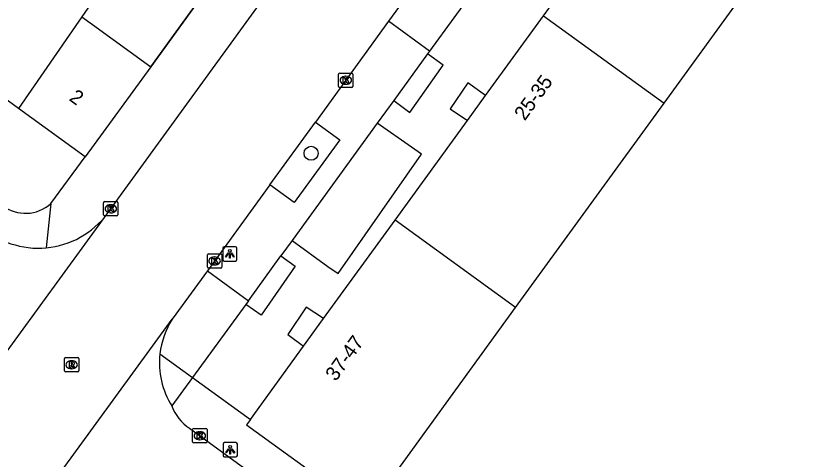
# Model space of a CAD drawing. Extents: x 159675 to 160530, y 382179 to 382901.
# Drawn here: x 160284.3 to 160339.1, y 382588.5 to 382619.4 of the extents above; entities that cross this region are included whole.
import ezdxf

# ---------------------------------------------------------------- set-up
doc = ezdxf.new("R2010")
doc.units = 0
for name, color, linetype in [('IMGEO_Boom', 7, 'Continuous'), ('IMGEO_Kolk', 7, 'Continuous'), ('IMGEO_Lichtpunt', 7, 'Continuous'), ('IMGEO_Muur', 7, 'Continuous'), ('IMGEO_Pand', 7, 'Continuous'), ('IMGEO_Pand_nummerreeks', 7, 'Continuous'), ('IMGEO_Rijbaan_lokaal_gesloten', 7, 'Continuous'), ('IMGEO_Rijbaan_lokaal_open', 7, 'Continuous'), ('IMGEO_Rioolput', 7, 'Continuous'), ('IMGEO_Voetpad_open', 7, 'Continuous')]:
    doc.layers.add(name, color=color, linetype=linetype)

msp = doc.modelspace()

# ---------------------------------------------------------------- linework, layer by layer
at = {"layer": 'IMGEO_Boom'}
msp.add_circle((160304.817, 382609.777), 0.489, dxfattribs=at)
at = {"layer": 'IMGEO_Kolk'}
for p, q in [((160306.806, 382615.366), (160307.658, 382615.366)), ((160306.731, 382614.44), (160306.731, 382615.292)), ((160307.219, 382615.146), (160307.244, 382615.146)), ((160307.732, 382615.292), (160307.732, 382614.44)), ((160307.658, 382614.366), (160306.806, 382614.366)), ((160307.242, 382614.586), (160307.217, 382614.586)), ((160290.37, 382605.485), (160290.37, 382606.337)), ((160290.445, 382606.411), (160291.297, 382606.411)), ((160290.858, 382606.191), (160290.883, 382606.191)), ((160291.371, 382606.337), (160291.371, 382605.485)), ((160290.881, 382605.631), (160290.856, 382605.631)), ((160291.297, 382605.411), (160290.445, 382605.411)), ((160297.671, 382602.781), (160298.523, 382602.781)), ((160297.596, 382601.855), (160297.596, 382602.707)), ((160298.084, 382602.561), (160298.109, 382602.561)), ((160298.597, 382602.707), (160298.597, 382601.855)), ((160298.523, 382601.781), (160297.671, 382601.781)), ((160298.107, 382602.001), (160298.082, 382602.001)), ((160296.569, 382589.673), (160296.569, 382590.525)), ((160296.644, 382590.599), (160297.496, 382590.599)), ((160297.057, 382590.379), (160297.082, 382590.379)), ((160297.57, 382590.525), (160297.57, 382589.673)), ((160297.496, 382589.599), (160296.644, 382589.599)), ((160297.08, 382589.819), (160297.055, 382589.819))]:
    msp.add_line(p, q, dxfattribs=at)
for points in [[(160306.806, 382615.366), (160307.658, 382615.366)], [(160306.731, 382614.44), (160306.731, 382615.292)], [(160307.052, 382615.066), (160307.175, 382615.066), (160307.175, 382614.915), (160307.305, 382615.066), (160307.469, 382615.066), (160307.323, 382614.915), (160307.476, 382614.666), (160307.324, 382614.666), (160307.239, 382614.83), (160307.175, 382614.763), (160307.175, 382614.666), (160307.052, 382614.666), (160307.052, 382615.066)], [(160307.732, 382615.292), (160307.732, 382614.44)], [(160307.658, 382614.366), (160306.806, 382614.366)], [(160290.37, 382605.485), (160290.37, 382606.337)], [(160290.445, 382606.411), (160291.297, 382606.411)], [(160290.691, 382606.111), (160290.814, 382606.111), (160290.814, 382605.96), (160290.944, 382606.111), (160291.108, 382606.111), (160290.962, 382605.96), (160291.115, 382605.711), (160290.963, 382605.711), (160290.878, 382605.875), (160290.814, 382605.808), (160290.814, 382605.711), (160290.691, 382605.711), (160290.691, 382606.111)], [(160291.371, 382606.337), (160291.371, 382605.485)], [(160291.297, 382605.411), (160290.445, 382605.411)], [(160297.671, 382602.781), (160298.523, 382602.781)], [(160297.596, 382601.855), (160297.596, 382602.707)], [(160297.917, 382602.481), (160298.04, 382602.481), (160298.04, 382602.33), (160298.17, 382602.481), (160298.334, 382602.481), (160298.188, 382602.33), (160298.341, 382602.081), (160298.189, 382602.081), (160298.104, 382602.245), (160298.04, 382602.178), (160298.04, 382602.081), (160297.917, 382602.081), (160297.917, 382602.481)], [(160298.597, 382602.707), (160298.597, 382601.855)], [(160298.523, 382601.781), (160297.671, 382601.781)], [(160296.569, 382589.673), (160296.569, 382590.525)], [(160296.644, 382590.599), (160297.496, 382590.599)], [(160296.89, 382590.299), (160297.013, 382590.299), (160297.013, 382590.148), (160297.143, 382590.299), (160297.307, 382590.299), (160297.161, 382590.148), (160297.314, 382589.899), (160297.162, 382589.899), (160297.077, 382590.063), (160297.013, 382589.996), (160297.013, 382589.899), (160296.89, 382589.899), (160296.89, 382590.299)], [(160297.57, 382590.525), (160297.57, 382589.673)], [(160297.496, 382589.599), (160296.644, 382589.599)]]:
    msp.add_lwpolyline(points, dxfattribs=at)
for centre, start, end in [((160306.808, 382615.29), 91.552, 178.448), ((160306.808, 382615.29), 91.552, 178.448), ((160307.656, 382615.29), 1.552, 88.448), ((160307.656, 382615.29), 1.552, 88.448), ((160306.808, 382614.442), 181.552, 268.448), ((160306.808, 382614.442), 181.552, 268.448), ((160307.656, 382614.442), 271.552, 358.448), ((160307.656, 382614.442), 271.552, 358.448), ((160290.447, 382606.335), 91.552, 178.448), ((160290.447, 382606.335), 91.552, 178.448), ((160291.295, 382606.335), 1.552, 88.448), ((160291.295, 382606.335), 1.552, 88.448), ((160290.447, 382605.487), 181.552, 268.448), ((160290.447, 382605.487), 181.552, 268.448), ((160291.295, 382605.487), 271.552, 358.448), ((160291.295, 382605.487), 271.552, 358.448), ((160297.673, 382602.705), 91.552, 178.448), ((160297.673, 382602.705), 91.552, 178.448), ((160298.521, 382602.705), 1.552, 88.448), ((160298.521, 382602.705), 1.552, 88.448), ((160297.673, 382601.857), 181.552, 268.448), ((160297.673, 382601.857), 181.552, 268.448), ((160298.521, 382601.857), 271.552, 358.448), ((160298.521, 382601.857), 271.552, 358.448), ((160296.646, 382590.523), 91.552, 178.448), ((160296.646, 382590.523), 91.552, 178.448), ((160297.494, 382590.523), 1.552, 88.448), ((160297.494, 382590.523), 1.552, 88.448), ((160296.646, 382589.675), 181.552, 268.448), ((160296.646, 382589.675), 181.552, 268.448), ((160297.494, 382589.675), 271.552, 358.448), ((160297.494, 382589.675), 271.552, 358.448)]:
    msp.add_arc(centre, 0.0765, start, end, dxfattribs=at)
for centre, major_axis, ratio, start_param, end_param in [((160307.218, 382614.866), (-0.387, 0.002), 0.722429, 4.712389, 7.853982), ((160307.243, 382614.866), (-0.39, 0.002), 0.717154, 1.570796, 4.712389), ((160290.857, 382605.911), (-0.387, 0.002), 0.722429, 4.712389, 7.853982), ((160290.882, 382605.911), (-0.39, 0.002), 0.717154, 1.570796, 4.712389), ((160298.083, 382602.281), (-0.387, 0.002), 0.722429, 4.712389, 7.853982), ((160298.108, 382602.281), (-0.39, 0.002), 0.717154, 1.570796, 4.712389), ((160297.056, 382590.099), (-0.387, 0.002), 0.722429, 4.712389, 7.853982), ((160297.081, 382590.099), (-0.39, 0.002), 0.717154, 1.570796, 4.712389)]:
    msp.add_ellipse(centre, major_axis=major_axis, ratio=ratio, start_param=start_param, end_param=end_param, dxfattribs=at)
at = {"layer": 'IMGEO_Lichtpunt'}
for p, q in [((160299.563, 382603.269), (160298.755, 382603.269)), ((160299.563, 382603.269), (160298.755, 382603.269)), ((160298.661, 382603.174), (160298.661, 382602.367)), ((160298.661, 382603.174), (160298.661, 382602.367)), ((160299.657, 382602.367), (160299.657, 382603.174)), ((160299.657, 382602.367), (160299.657, 382603.174)), ((160298.755, 382602.273), (160299.563, 382602.273)), ((160298.755, 382602.273), (160299.563, 382602.273)), ((160299.588, 382589.617), (160298.78, 382589.617)), ((160299.588, 382589.617), (160298.78, 382589.617)), ((160298.686, 382589.522), (160298.686, 382588.715)), ((160298.686, 382589.522), (160298.686, 382588.715)), ((160299.682, 382588.715), (160299.682, 382589.522)), ((160299.682, 382588.715), (160299.682, 382589.522)), ((160298.78, 382588.621), (160299.588, 382588.621)), ((160298.78, 382588.621), (160299.588, 382588.621))]:
    msp.add_line(p, q, dxfattribs=at)
for points in [[(160299.035, 382602.838), (160299.074, 382602.81), (160298.886, 382602.548), (160298.848, 382602.575), (160299.035, 382602.838)], [(160299.137, 382602.79), (160299.184, 382602.79), (160299.184, 382602.468), (160299.137, 382602.468), (160299.137, 382602.79)], [(160299.247, 382602.81), (160299.285, 382602.837), (160299.472, 382602.575), (160299.433, 382602.547), (160299.247, 382602.81)], [(160299.06, 382589.186), (160299.099, 382589.158), (160298.911, 382588.896), (160298.873, 382588.923), (160299.06, 382589.186)], [(160299.162, 382589.138), (160299.209, 382589.138), (160299.209, 382588.816), (160299.162, 382588.816), (160299.162, 382589.138)], [(160299.272, 382589.158), (160299.31, 382589.185), (160299.497, 382588.923), (160299.458, 382588.895), (160299.272, 382589.158)]]:
    msp.add_lwpolyline(points, dxfattribs=at)
for centre in [(160299.16, 382602.972), (160299.185, 382589.32)]:
    msp.add_circle(centre, 0.0994, dxfattribs=at)
for centre, start, end in [((160298.755, 382603.174), 90, 180), ((160298.755, 382603.174), 90, 180), ((160299.563, 382603.174), 0, 90), ((160299.563, 382603.174), 0, 90), ((160298.755, 382602.367), 180, 270), ((160298.755, 382602.367), 180, 270), ((160299.563, 382602.367), 270, 0), ((160299.563, 382602.367), 270, 360), ((160298.78, 382589.522), 90, 180), ((160298.78, 382589.522), 90, 180), ((160299.588, 382589.522), 0, 90), ((160299.588, 382589.522), 0, 90), ((160298.78, 382588.715), 180, 270), ((160298.78, 382588.715), 180, 270), ((160299.588, 382588.715), 270, 0), ((160299.588, 382588.715), 270, 360)]:
    msp.add_arc(centre, 0.0946, start, end, dxfattribs=at)
at = {"layer": 'IMGEO_Muur'}
msp.add_lwpolyline([(160293.648, 382615.802), (160299.627, 382624.071)], dxfattribs=at)
at = {"layer": 'IMGEO_Pand'}
for points in [[(160329.387, 382613.273), (160339.718, 382627.522)], [(160284.088, 382622.763), (160285.838, 382625.288), (160290.642, 382621.897), (160288.85, 382619.295)], [(160320.991, 382619.361), (160324.966, 382624.844)], [(160288.85, 382619.295), (160284.451, 382612.91)], [(160288.85, 382619.295), (160289.606, 382618.745), (160293.648, 382615.802)], [(160316.956, 382613.796), (160320.991, 382619.361)], [(160320.991, 382619.361), (160329.387, 382613.273)], [(160284.451, 382612.91), (160279.618, 382616.429)], [(160293.648, 382615.802), (160289.085, 382609.536)], [(160315.694, 382612.056), (160316.956, 382613.796)], [(160319.055, 382599.025), (160329.387, 382613.273)], [(160289.085, 382609.536), (160284.451, 382612.91)], [(160310.659, 382605.113), (160315.694, 382612.056)], [(160305.689, 382598.258), (160310.659, 382605.113)], [(160319.055, 382599.025), (160310.659, 382605.113)], [(160300.591, 382591.227), (160300.328, 382590.864), (160308.724, 382584.776), (160319.055, 382599.025)], [(160304.297, 382596.339), (160305.689, 382598.258)], [(160300.591, 382591.227), (160304.297, 382596.339)]]:
    msp.add_lwpolyline(points, dxfattribs=at)
at = {"layer": 'IMGEO_Rijbaan_lokaal_gesloten'}
for points in [[(160318.081, 382629.815), (160314.718, 382625.182), (160313.661, 382623.726), (160310.216, 382618.98)], [(160290.62, 382605.563), (160302.639, 382622.143)], [(160310.216, 382618.98), (160305.116, 382611.954)], [(160301.944, 382607.584), (160305.116, 382611.954)], [(160301.944, 382607.584), (160297.594, 382601.591)], [(160279.709, 382590.612), (160290.62, 382605.563)], [(160297.594, 382601.591), (160295.155, 382598.231)], [(160285.942, 382585.556), (160295.155, 382598.231)]]:
    msp.add_lwpolyline(points, dxfattribs=at)
at = {"layer": 'IMGEO_Rijbaan_lokaal_open'}
msp.add_lwpolyline([(160296.348, 382590.626), (160318.778, 382574.273)], dxfattribs=at)
for centre, radius, start, end in [((160285.83, 382609.149), 5.983, 275.26, 323.1767), ((160285.829, 382609.154), 5.989, 227.3876, 275.2653), ((160299.924, 382595.176), 5.663, 147.3539, 173.6526), ((160299.906, 382595.174), 5.646, 173.6175, 212.1343), ((160298.017, 382593.204), 3.071, 199.6505, 237.0788)]:
    msp.add_arc(centre, radius, start, end, dxfattribs=at)
at = {"layer": 'IMGEO_Rioolput'}
for p, q in [((160287.645, 382594.62), (160287.645, 382595.472)), ((160287.72, 382595.546), (160288.572, 382595.546)), ((160288.133, 382595.326), (160288.158, 382595.326)), ((160288.646, 382595.472), (160288.646, 382594.62)), ((160288.572, 382594.546), (160287.72, 382594.546)), ((160288.156, 382594.766), (160288.131, 382594.766))]:
    msp.add_line(p, q, dxfattribs=at)
for points in [[(160287.645, 382594.62), (160287.645, 382595.472)], [(160287.72, 382595.546), (160288.572, 382595.546)], [(160288.234, 382595.244), (160287.982, 382595.246), (160287.982, 382594.846)], [(160288.16, 382595.165), (160288.106, 382595.165), (160288.106, 382595.084)], [(160288.106, 382595.084), (160288.158, 382595.084)], [(160288.646, 382595.472), (160288.646, 382594.62)], [(160288.572, 382594.546), (160287.72, 382594.546)], [(160287.982, 382594.846), (160288.106, 382594.846), (160288.106, 382595.008), (160288.117, 382595.008)], [(160288.164, 382594.979), (160288.235, 382594.846), (160288.375, 382594.846), (160288.31, 382594.972)]]:
    msp.add_lwpolyline(points, dxfattribs=at)
for centre, radius, start, end in [((160287.722, 382595.47), 0.0765, 91.552, 178.448), ((160287.722, 382595.47), 0.0765, 91.552, 178.448), ((160288.142, 382595.273), 0.19, 274.7715, 282.9687), ((160288.166, 382595.069), 0.0964, 77.0061, 93.1865), ((160288.18, 382595.126), 0.0378, 276.6634, 79.6772), ((160288.233, 382595.134), 0.109, 350.3612, 89.416), ((160288.231, 382595.134), 0.112, 277.5842, 350.9817), ((160288.57, 382595.47), 0.0765, 1.552, 88.448), ((160288.57, 382595.47), 0.0765, 1.552, 88.448), ((160287.722, 382594.622), 0.0765, 181.552, 268.448), ((160287.722, 382594.622), 0.0765, 181.552, 268.448), ((160288.116, 382594.955), 0.0533, 26.0293, 88.6989), ((160288.215, 382594.919), 0.108, 29.5134, 73.7905), ((160288.57, 382594.622), 0.0765, 271.552, 358.448), ((160288.57, 382594.622), 0.0765, 271.552, 358.448)]:
    msp.add_arc(centre, radius, start, end, dxfattribs=at)
for centre, major_axis, ratio, start_param, end_param in [((160288.132, 382595.046), (-0.387, 0.002), 0.722429, 4.712389, 7.853982), ((160288.157, 382595.046), (-0.39, 0.002), 0.717154, 1.570796, 4.712389)]:
    msp.add_ellipse(centre, major_axis=major_axis, ratio=ratio, start_param=start_param, end_param=end_param, dxfattribs=at)
at = {"layer": 'IMGEO_Voetpad_open'}
for points in [[(160299.627, 382624.071), (160293.648, 382615.802)], [(160316.452, 382621.559), (160313.066, 382616.893)], [(160313.066, 382616.893), (160310.216, 382618.98)], [(160312.924, 382616.698), (160310.567, 382613.449)], [(160310.567, 382613.449), (160311.698, 382612.628), (160314.02, 382615.926), (160312.924, 382616.698)], [(160313.066, 382616.893), (160312.924, 382616.698)], [(160316.956, 382613.796), (160315.735, 382614.681), (160314.493, 382612.887), (160315.694, 382612.056)], [(160310.567, 382613.449), (160309.422, 382611.872)], [(160305.116, 382611.954), (160306.817, 382610.719), (160303.645, 382606.349), (160301.944, 382607.584)], [(160309.422, 382611.872), (160303.496, 382603.706)], [(160303.496, 382603.706), (160305.988, 382601.897), (160306.692, 382601.405), (160312.501, 382609.723), (160311.796, 382610.215), (160309.422, 382611.872)], [(160286.703, 382606.273), (160289.085, 382609.536)], [(160286.703, 382606.273), (160286.379, 382603.191)], [(160303.496, 382603.706), (160302.715, 382602.63)], [(160302.715, 382602.63), (160303.717, 382601.903), (160301.344, 382598.5), (160300.264, 382599.252)], [(160300.449, 382599.507), (160302.715, 382602.63)], [(160297.594, 382601.591), (160300.449, 382599.507)], [(160300.449, 382599.507), (160300.264, 382599.252)], [(160300.264, 382599.252), (160296.561, 382594.149)], [(160305.689, 382598.258), (160304.47, 382599.068), (160303.19, 382597.142), (160304.297, 382596.339)], [(160294.295, 382595.802), (160296.561, 382594.149)], [(160296.561, 382594.149), (160295.125, 382592.171)], [(160296.561, 382594.149), (160300.591, 382591.227)]]:
    msp.add_lwpolyline(points, dxfattribs=at)
msp.add_arc((160284.937, 382608.241), 2.644, 232.6194, 311.8994, dxfattribs=at)

# ---------------------------------------------------------------- texts
at = {"layer": 'IMGEO_Pand_nummerreeks'}
for s, rotation, p in [('25-35', 54.2075, (160319.69, 382611.993)), ('2', 323.9415, (160287.911, 382613.508)), ('37-47', 54.0528, (160306.537, 382593.84))]:
    msp.add_text(s, height=1, rotation=rotation, dxfattribs=at).set_placement(p)

doc.saveas('drawing.dxf')
